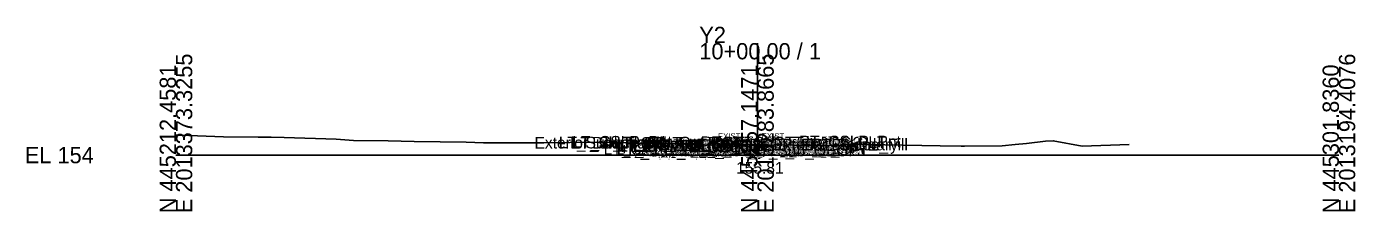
# Model space of a CAD drawing. Extents: x -26 to 203, y -10 to 6017.
# Drawn here: x -25.7 to 202.8, y -9.7 to 22.1 of the extents above; entities that cross this region are included whole.
import ezdxf

# ---------------------------------------------------------------- set-up
doc = ezdxf.new("R2010")
doc.units = 0
for name, color, linetype in [('Default', 7, 'Continuous'), ('Exist Cross Section Cell', 7, 'Continuous'), ('Exist XS Center Line Elevation Label', 7, 'Continuous'), ('Exist XS Ground Line', 7, 'Continuous'), ('Prop XS SE Text', 7, 'Continuous'), ('Scratch_Level_0', 7, 'Continuous')]:
    doc.layers.add(name, color=color, linetype=linetype)

msp = doc.modelspace()

# ---------------------------------------------------------------- linework, layer by layer
at = {"layer": 'Exist Cross Section Cell'}
for p, q in [((100, 0), (100, 19.29)), ((0, 0), (100, 0)), ((100, 0), (200, 0))]:
    msp.add_line(p, q, dxfattribs=at)
at = {"layer": 'Exist XS Ground Line'}
msp.add_lwpolyline([(0, 3.44), (0.72, 3.41), (5.2, 3.24), (8.18, 3.14), (14.14, 3.1), (16.38, 3.1), (18.61, 3.01), (27.56, 2.74), (30.55, 2.54), (36.52, 2.47), (40.95, 2.37), (49.92, 2.25), (52.91, 2.14), (58.9, 2.14), (63.29, 2.14), (72.28, 2.25), (85.73, 1.96), (87.63, 1.92), (88.22, 1.92), (90.38, 1.71), (100.15, 1.81), (100.67, 1.8), (106.27, 1.74), (113.58, 1.67), (115.54, 1.86), (131.45, 1.63), (135.02, 1.55), (135.61, 1.55), (142.09, 1.59), (144.35, 1.82), (146.29, 2.02), (149.55, 2.38), (150.86, 2.49), (155.86, 1.55), (163.95, 1.82)], dxfattribs=at)

# ---------------------------------------------------------------- texts
at = {"layer": 'Default'}
msp.add_text('-', height=0.0001, dxfattribs=at).set_placement((0, 0))
at = {"layer": 'Exist Cross Section Cell'}
for s, p in [('Y2', (90, 19.29)), ('10+00.00 / 1', (90, 16.49)), ('EL 154', (-26, -1.4))]:
    msp.add_text(s, height=2.8, dxfattribs=at).set_placement(p)
for s, p in [('E 2013373.3255', (2.8, -10)), ('E 2013283.8665', (102.8, -10)), ('E 2013194.4076', (202.8, -10)), ('N 445212.4581', (0, -10)), ('N 445257.1471', (100, -10)), ('N 445301.8360', (200, -10))]:
    msp.add_text(s, height=2.8, rotation=90, dxfattribs=at).set_placement(p)
at = {"layer": 'Exist XS Center Line Elevation Label'}
msp.add_text('155.81', height=2, dxfattribs=at).set_placement((96.32, -3.19))
at = {"layer": 'Prop XS SE Text'}
for rotation, p in [(0.5729, (93.22, 2.74)), (359.4271, (100.74, 2.8))]:
    msp.add_text('EXIST.', height=1, rotation=rotation, dxfattribs=at).set_placement(p)
at = {"layer": 'Scratch_Level_0'}
for s, p in [('Exterior Boundary', (61.66, 1.14)), ('LT_Sub_Trench_Out_DLT', (65.84, 1.16)), ('LT_Slope_Fill', (68.04, 1.14)), ('LT_CSLP_Pnt', (68.17, 1.3)), ('LT_CG_Top_Face', (75.26, 1.11)), ('LT_CG_Top_BOC', (75.78, 1.11)), ('LT_PV_Sub_Tie_Out', (75.96, 0.72)), ('LT_CG_Top_Gut', (76.24, 0.61)), ('LT_PV_OEEOP_EG', (78.54, 0.72)), ('LT_PV2_OEOT', (80.17, 0.46)), ('LT_PV2_OEEOP', (80.31, 0.47)), ('LT_PV1_OEOT', (80.74, 0.71)), ('LT_PV1_OEEOP', (80.87, 0.6)), ('LT_PV_IEEOP_EG', (88.19, 0.81)), ('RT_PV2_OEEOP', (89.26, 0.56)), ('RT_PV1_OEEOP', (89.83, 0.69)), ('RT_PV2_IEEOP', (89.91, 0.56)), ('LT_PV2_IEEOP', (89.95, 0.56)), ('RT_Sub_Trench_Out_DLT', (90.25, 1.21)), ('RT_PV1_IEEOP', (90.47, 0.69)), ('LT_PV1_IEEOP', (90.52, 0.69)), ('PV2_PGL', (93.91, 0.56)), ('RT_CG_Top_Face', (94.21, 1.16)), ('PV1_PGL', (94.47, 0.81)), ('RT_PV2_OEOT', (95.13, 0.51)), ('RT_CG_Top_Gut', (95.19, 0.66)), ('RT_PV1_OEOT', (95.69, 0.76)), ('RT_CG_Top_BOC', (95.74, 1.16)), ('Exterior Boundary', (102.75, 0.82)), ('RT_CSLP_Pnt', (107.13, 1.35)), ('RT_Slope_Fill', (109.08, 0.82)), ('LT_CG1_Shelf_Out', (73.55, 0.1)), ('LT_CG_Bot_BOC', (75.81, 0.1)), ('LT_Sub_OEOP', (76.77, -0.24)), ('LT_CG_Bot_IE', (79.91, 0.13)), ('LT_Sub_OEOT', (80.08, -0.21)), ('LT_PV3_OEOT', (80.17, 0.13)), ('LT_Sub_OEEOP', (80.21, -0.2)), ('LT_PV3_OEEOP', (80.31, 0.14)), ('RT_Sub_OEEOP', (89.17, -0.11)), ('RT_PV3_OEEOP', (89.26, 0.23)), ('LT_PV3_IEEOP', (89.95, 0.23)), ('RT_CG1_Shelf_Out', (94.5, 0.15)), ('RT_CG_Bot_IE', (94.87, 0.18)), ('RT_Sub_OEOT', (95.03, -0.16)), ('RT_PV3_OEOT', (95.13, 0.18)), ('RT_CG_Bot_BOC', (95.77, 0.15)), ('RT_Sub_OEOP', (98.4, -0.19))]:
    msp.add_text(s, height=2, dxfattribs=at).set_placement(p)

doc.saveas('drawing.dxf')
